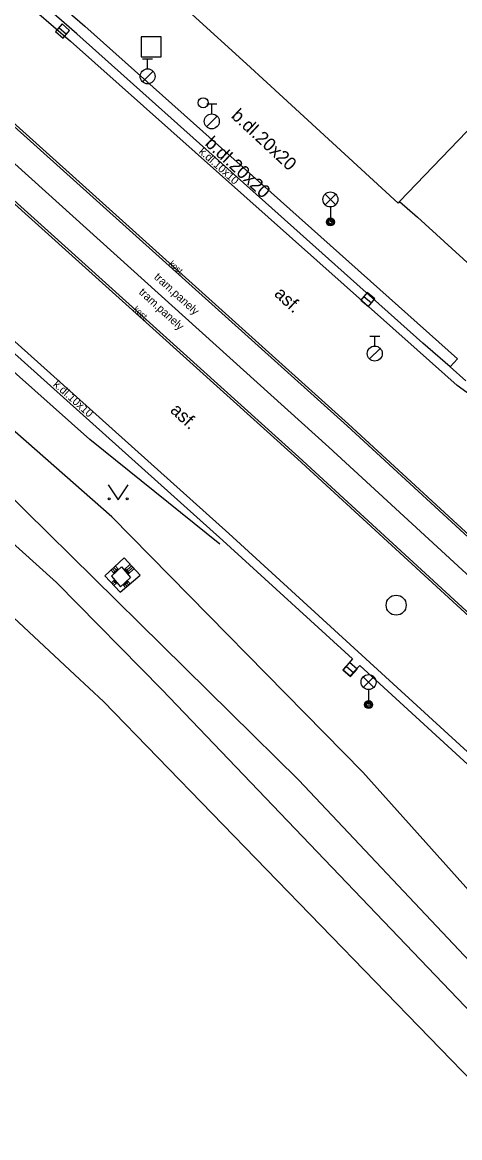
# Model space of a CAD drawing. Extents: x -598932 to -598196, y -1162207 to -1161504.
# Drawn here: x -598839 to -598817.1, y -1161799.2 to -1161743.4 of the extents above; entities that cross this region are included whole.
import ezdxf

# ---------------------------------------------------------------- set-up
doc = ezdxf.new("R2010")
doc.units = 0
for name, color, linetype in [('Level 26', 7, 'Continuous'), ('Level 27', 7, 'Continuous'), ('Level 28', 7, 'Continuous'), ('Level 33', 7, 'Continuous'), ('Level 36', 7, 'Continuous'), ('neurcene site - povrch.  znaky - skut. stav', 7, 'Continuous'), ('specificka linie pasportu komunikaci', 7, 'Continuous'), ('TM - budovy zdene_ betonove - VP', 7, 'Continuous'), ('TM - CD - osa koleji', 7, 'Continuous'), ('TM - hladina vodniho toku_ bazenu_ nadrze', 7, 'Continuous'), ('TM - horni hrana svahu', 7, 'Continuous'), ('TM - komunikace - VP', 7, 'Continuous'), ('TM - letecke snimky - pomocna linie', 7, 'Continuous'), ('TM - plot dreveny_ kovovy - VP', 7, 'Continuous'), ('TM - popis povrchu', 7, 'Continuous'), ('TM - rozhrani mezi zpev. plochami mezi sebou - VP', 7, 'Continuous'), ('TM - rozhrani ploch obecne - VP', 7, 'Continuous'), ('TM - srafovani', 7, 'Continuous'), ('TM - svodidlo jednostranne - VP', 7, 'Continuous'), ('TM - vjezd na pozemek', 7, 'Continuous'), ('TM - zabradli - VP', 7, 'Continuous')]:
    doc.layers.add(name, color=color, linetype=linetype)

msp = doc.modelspace()

# ---------------------------------------------------------------- linework, layer by layer
at = {"layer": 'Level 26'}
msp.add_lwpolyline([(-598833.05, -1161745.11), (-598832.05, -1161745.11), (-598832.05, -1161744.11), (-598833.05, -1161744.11)], close=True, dxfattribs=at)
at = {"layer": 'Level 27'}
for p, q in [((-598837.167, -1161743.654), (-598836.793, -1161743.986)), ((-598821.914, -1161757.092), (-598821.526, -1161757.408)), ((-598822.797, -1161775.584), (-598822.423, -1161775.916))]:
    msp.add_line(p, q, dxfattribs=at)
for points in [[(-598837.333, -1161743.84), (-598836.96, -1161744.173), (-598836.627, -1161743.8), (-598837, -1161743.467)], [(-598822.072, -1161757.285), (-598821.685, -1161757.602), (-598821.368, -1161757.215), (-598821.755, -1161756.898)], [(-598822.963, -1161775.77), (-598822.59, -1161776.103), (-598822.257, -1161775.73), (-598822.63, -1161775.397)]]:
    msp.add_lwpolyline(points, close=True, dxfattribs=at)
msp.add_circle((-598820.3, -1161772.53), 0.5, dxfattribs=at)
at = {"layer": 'Level 28'}
for p, q in [((-598832.98, -1161745.215), (-598832.48, -1161745.215)), ((-598832.73, -1161745.715), (-598832.73, -1161745.215)), ((-598832.988, -1161746.362), (-598832.458, -1161745.832)), ((-598829.77, -1161747.465), (-598829.27, -1161747.465)), ((-598829.52, -1161747.965), (-598829.52, -1161747.465)), ((-598829.778, -1161748.612), (-598829.248, -1161748.082)), ((-598821.62, -1161759.075), (-598821.12, -1161759.075)), ((-598821.37, -1161759.575), (-598821.37, -1161759.075)), ((-598821.628, -1161760.222), (-598821.098, -1161759.692))]:
    msp.add_line(p, q, dxfattribs=at)
for centre, radius in [((-598832.73, -1161746.09), 0.375), ((-598829.95, -1161747.41), 0.25), ((-598829.52, -1161748.34), 0.375), ((-598821.37, -1161759.95), 0.375)]:
    msp.add_circle(centre, radius, dxfattribs=at)
at = {"layer": 'Level 33'}
for p, q in [((-598823.855, -1161752.51), (-598823.325, -1161751.98)), ((-598823.855, -1161751.98), (-598823.325, -1161752.51)), ((-598823.59, -1161752.62), (-598823.59, -1161753.37)), ((-598821.945, -1161776.64), (-598821.415, -1161776.11)), ((-598821.945, -1161776.11), (-598821.415, -1161776.64)), ((-598821.68, -1161776.75), (-598821.68, -1161777.5))]:
    msp.add_line(p, q, dxfattribs=at)
for centre, radius in [((-598823.59, -1161752.245), 0.375), ((-598823.59, -1161753.37), 0.2), ((-598823.59, -1161753.37), 0.145), ((-598823.59, -1161753.37), 0.0876), ((-598821.68, -1161776.375), 0.375), ((-598821.68, -1161777.5), 0.2), ((-598821.68, -1161777.5), 0.145), ((-598821.68, -1161777.5), 0.0876)]:
    msp.add_circle(centre, radius, dxfattribs=at)
at = {"layer": 'Level 36'}
msp.add_lwpolyline([(-598834.7, -1161766.51), (-598834.2, -1161767.26), (-598833.7, -1161766.51)], dxfattribs=at)
for centre in [(-598834.65, -1161767.21), (-598833.751, -1161767.21)]:
    msp.add_circle(centre, 0.05, dxfattribs=at)
at = {"layer": 'neurcene site - povrch.  znaky - skut. stav'}
for points in [[(-598834.54, -1161771.08), (-598834.03, -1161770.61)], [(-598834.03, -1161770.61), (-598833.58, -1161771.14)], [(-598834.54, -1161771.08), (-598834.09, -1161771.61)], [(-598834.09, -1161771.61), (-598833.58, -1161771.14)]]:
    msp.add_lwpolyline(points, dxfattribs=at)
at = {"layer": 'specificka linie pasportu komunikaci'}
msp.add_lwpolyline([(-598817.6, -1161760.62), (-598817.24, -1161760.22)], dxfattribs=at)
at = {"layer": 'TM - budovy zdene_ betonove - VP'}
for points in [[(-598827.79, -1161745.47), (-598833.21, -1161740.51), (-598833.8, -1161739.97)], [(-598827.79, -1161745.47), (-598826.77, -1161746.4)], [(-598826.77, -1161746.4), (-598820.2, -1161752.43)], [(-598814.25, -1161746.23), (-598820.13, -1161752.35)], [(-598820.13, -1161752.35), (-598820.2, -1161752.43)]]:
    msp.add_lwpolyline(points, dxfattribs=at)
at = {"layer": 'TM - CD - osa koleji'}
for points in [[(-598823.67, -1161764.63), (-598840.76, -1161749.23)], [(-598823.67, -1161764.63), (-598809.08, -1161778.04), (-598795.12, -1161790.98), (-598780.98, -1161804.03), (-598752.01, -1161830.97), (-598740.39, -1161841.76), (-598737.43, -1161844.53), (-598720.51, -1161860.13)]]:
    msp.add_lwpolyline(points, dxfattribs=at)
at = {"layer": 'TM - hladina vodniho toku_ bazenu_ nadrze'}
msp.add_lwpolyline([(-598720.27, -1161904.76), (-598749.26, -1161871.38), (-598790.83, -1161824.98), (-598815.91, -1161796.95), (-598834.93, -1161777.35), (-598836.37, -1161776.01), (-598850.71, -1161762.63), (-598866.62, -1161749.21), (-598892.99, -1161728.98)], dxfattribs=at)
at = {"layer": 'TM - horni hrana svahu'}
msp.add_lwpolyline([(-598932.017, -1161697.604), (-598929.76, -1161698.95), (-598888.91, -1161727.38), (-598861.19, -1161748.52), (-598845.68, -1161761.08), (-598825.16, -1161781.28), (-598808.06, -1161799.42), (-598788.14, -1161822.37), (-598765.72, -1161848.31), (-598730.99, -1161888.48), (-598729.85, -1161889.88)], dxfattribs=at)
at = {"layer": 'TM - komunikace - VP'}
for points in [[(-598816.81, -1161761.32), (-598817.6, -1161760.62), (-598818.96, -1161759.43), (-598836.26, -1161743.96), (-598839.2, -1161741.39)], [(-598845.59, -1161754.76), (-598845.41, -1161754.57), (-598828.96, -1161769.3), (-598822.48, -1161775.21), (-598822.95, -1161775.76), (-598822.6, -1161776.07), (-598822.11, -1161775.55), (-598813.72, -1161783.25), (-598807.19, -1161789.23)]]:
    msp.add_lwpolyline(points, dxfattribs=at)
at = {"layer": 'TM - letecke snimky - pomocna linie'}
for points in [[(-598889.27, -1161728.96), (-598867.09, -1161745.78), (-598851.9, -1161758.23), (-598837.29, -1161771.39), (-598832, -1161776.77)], [(-598832, -1161776.77), (-598807.26, -1161802.61)]]:
    msp.add_lwpolyline(points, dxfattribs=at)
at = {"layer": 'TM - plot dreveny_ kovovy - VP'}
msp.add_lwpolyline([(-598819.24, -1161753.13), (-598815.23, -1161756.78)], dxfattribs=at)
at = {"layer": 'TM - rozhrani mezi zpev. plochami mezi sebou - VP'}
for points in [[(-598852.05, -1161731.2), (-598846.86, -1161735.54), (-598841.7, -1161739.91), (-598836.58, -1161744.33)], [(-598838.84, -1161740.99), (-598835.87, -1161743.58), (-598817.24, -1161760.22)], [(-598817.25, -1161761.55), (-598819.25, -1161759.77), (-598836.58, -1161744.33)], [(-598839.9, -1161748.14), (-598822.75, -1161763.56), (-598808.13, -1161777.02)], [(-598839.8, -1161748.08), (-598822.68, -1161763.48), (-598808.05, -1161776.94)], [(-598841.73, -1161750.36), (-598825.23, -1161765.21), (-598810.12, -1161779.09)], [(-598841.63, -1161750.3), (-598825.16, -1161765.13), (-598810.05, -1161779.01), (-598804.38, -1161784.26)], [(-598845.05, -1161754.27), (-598828.66, -1161768.95), (-598813.4, -1161782.91), (-598806.77, -1161788.96)], [(-598815.76, -1161762.19), (-598816.21, -1161762.12), (-598816.76, -1161761.89), (-598817.25, -1161761.55)]]:
    msp.add_lwpolyline(points, dxfattribs=at)
at = {"layer": 'TM - rozhrani ploch obecne - VP'}
for points in [[(-598834.86, -1161771.07), (-598833.9, -1161770.17)], [(-598833.9, -1161770.17), (-598833.1, -1161771.03)], [(-598834.86, -1161771.07), (-598834.1, -1161771.88)], [(-598834.1, -1161771.88), (-598833.1, -1161771.03)]]:
    msp.add_lwpolyline(points, dxfattribs=at)
at = {"layer": 'TM - srafovani'}
for points in [[(-598834.33, -1161770.88), (-598834.48, -1161770.72)], [(-598834.25, -1161770.81), (-598834.41, -1161770.65)], [(-598834.18, -1161770.74), (-598834.33, -1161770.58)], [(-598834.21, -1161770.78), (-598834.27, -1161770.72)], [(-598833.9, -1161770.76), (-598833.61, -1161770.49)], [(-598833.84, -1161770.84), (-598833.54, -1161770.56)], [(-598833.77, -1161770.92), (-598833.47, -1161770.63)], [(-598833.71, -1161770.99), (-598833.4, -1161770.7)], [(-598834.4, -1161770.95), (-598834.55, -1161770.78)], [(-598834.39, -1161771.26), (-598834.54, -1161771.41)], [(-598834.36, -1161770.91), (-598834.41, -1161770.86)], [(-598834.29, -1161770.85), (-598834.34, -1161770.79)], [(-598833.87, -1161770.8), (-598833.79, -1161770.73)], [(-598833.81, -1161770.88), (-598833.72, -1161770.8)], [(-598833.74, -1161770.95), (-598833.66, -1161770.87)], [(-598834.33, -1161771.34), (-598834.48, -1161771.48)], [(-598834.36, -1161771.3), (-598834.42, -1161771.36)], [(-598834.26, -1161771.41), (-598834.41, -1161771.55)], [(-598834.29, -1161771.37), (-598834.35, -1161771.43)], [(-598833.97, -1161771.49), (-598833.83, -1161771.65)], [(-598833.93, -1161771.46), (-598833.87, -1161771.53)], [(-598833.89, -1161771.43), (-598833.76, -1161771.59)], [(-598833.86, -1161771.39), (-598833.8, -1161771.46)], [(-598833.82, -1161771.36), (-598833.68, -1161771.52)], [(-598833.78, -1161771.32), (-598833.72, -1161771.4)], [(-598833.75, -1161771.29), (-598833.6, -1161771.46)]]:
    msp.add_lwpolyline(points, dxfattribs=at)
at = {"layer": 'TM - svodidlo jednostranne - VP'}
for points in [[(-598835.62, -1161764.24), (-598843.89, -1161756.89)], [(-598829.11, -1161769.48), (-598835.62, -1161764.24)]]:
    msp.add_lwpolyline(points, dxfattribs=at)
at = {"layer": 'TM - vjezd na pozemek'}
msp.add_lwpolyline([(-598820.13, -1161752.35), (-598819.24, -1161753.13)], dxfattribs=at)
at = {"layer": 'TM - zabradli - VP'}
msp.add_lwpolyline([(-598806.23, -1161798.45), (-598821.96, -1161780.88), (-598834.52, -1161768.12), (-598854.43, -1161750.62)], dxfattribs=at)

# ---------------------------------------------------------------- texts
at = {"layer": 'TM - popis povrchu'}
for s, height, rotation, p in [('b.dl.20x20', 0.65, 317.075, (-598828.59, -1161748.12)), ('b.dl.20x20', 0.65, 317.075, (-598829.9, -1161749.5)), ('k.dl.10x10', 0.4, 318.0518, (-598830.2, -1161749.9)), ('kost.', 0.3, 317.6234, (-598831.68, -1161755.49)), ('tram.panely', 0.4, 317.7166, (-598832.44, -1161756.17)), ('tram.panely', 0.4, 317.7166, (-598833.2, -1161756.93)), ('asf.', 0.65, 317.22, (-598826.44, -1161757.02)), ('kost.', 0.3, 317.6234, (-598833.46, -1161757.76)), ('k.dl.10x10', 0.4, 318.0518, (-598837.48, -1161761.54)), ('asf.', 0.65, 317.22, (-598831.64, -1161762.84))]:
    msp.add_text(s, height=height, rotation=rotation, dxfattribs=at).set_placement(p)

doc.saveas('drawing.dxf')
